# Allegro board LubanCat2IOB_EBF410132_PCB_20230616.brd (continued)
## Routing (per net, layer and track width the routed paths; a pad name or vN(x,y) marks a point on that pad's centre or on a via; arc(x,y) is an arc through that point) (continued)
HDMI_TX_HPD_PORT: length 8.2
  TOP w0.156: R172.2 53.41,76.45 54.55,76.45 R176.1 D15.2 56.16,80.11 J21.19
HDMI_TX_HPDIN: length 32.5
  TOP w0.156: v1(52.72,69.72) 52.72,75.24 51.85,76.11 R172.1 ; J3.34 v1(40.28,57.94)
  BOTTOM w0.156: v1(52.72,69.72) 52.72,68.69 52.41,68.37 50.14,68.37 49.71,67.94 49.71,60.56 49.29,60.14 40.6,60.14 40.28,59.83 v1(40.28,57.94)
HDMI_TXCLKN_PORT: length 68.3
  TOP w0.124: J21.12 56.61,85.53 59.32,85.53 60.19,84.67 60.19,80.48 58.78,79.07 58.78,77.99 58.69,77.9 U31.5 U31.6 58.69,76.17 58.78,76.08 58.78,70.07 v1(58.48,69.77) ; v1(44.78,57) 44.28,57.5 J3.50
  ART04 w0.113: v1(44.78,57) 45.09,57.31 46.91,57.31 47.35,57.74 47.35,59.14 47.03,59.46 45.15,59.46 45.02,59.59 45.02,59.78 45.15,59.91 47.03,59.91 47.35,60.23 47.35,65.25 47.59,65.49 47.9,65.49 48.04,65.36 48.04,63.84 48.38,63.5 48.82,63.5 49.12,63.79 49.12,65.36 49.25,65.49 49.44,65.49 49.57,65.36 49.57,63.84 49.91,63.5 50.36,63.5 50.65,63.79 50.65,65.36 50.79,65.49 50.97,65.49 51.1,65.36 51.1,63.84 51.45,63.5 51.89,63.5 52.19,63.79 52.19,65.36 52.32,65.49 52.51,65.49 52.64,65.36 52.64,63.84 52.98,63.5 53.42,63.5 53.72,63.79 53.72,65.36 53.85,65.49 55.12,65.49 55.64,66.01 55.64,70.44 55.82,70.62 58.59,70.62 58.78,70.43 58.78,70.08 v1(58.48,69.77)
HDMI_TXCLKP_PORT: length 69.3
  TOP w0.124: v1(59.4,69.77) 59.33,69.77 59.1,70 59.1,70.32 arc(59.14,70.42) 59.24,70.46 arc(59.34,70.5) 59.39,70.6 59.39,70.82 arc(59.34,70.92) 59.24,70.96 arc(59.14,71) 59.1,71.1 59.1,71.31 arc(59.14,71.41) 59.24,71.45 arc(59.34,71.49) 59.39,71.59 59.39,71.81 arc(59.34,71.91) 59.24,71.95 arc(59.14,71.99) 59.1,72.09 59.1,72.3 arc(59.14,72.4) 59.24,72.45 arc(59.34,72.49) 59.39,72.59 59.39,72.8 arc(59.34,72.9) 59.24,72.94 arc(59.14,72.98) 59.1,73.08 59.1,76.08 59.19,76.17 U31.7 U31.4 59.19,77.9 59.1,77.99 59.1,78.93 60.51,80.34 60.51,84.8 59.46,85.86 56.61,85.86 J21.10 ; v1(44.78,57.93) 44.78,57.94 J3.52
  ART04 w0.113: v1(59.4,69.77) 59.1,70.08 59.1,70.57 58.72,70.94 55.69,70.94 55.32,70.57 55.32,66.14 54.99,65.81 53.72,65.81 53.41,65.49 53.41,63.92 53.29,63.81 53.11,63.81 52.96,63.97 52.96,65.49 52.64,65.81 52.19,65.81 51.87,65.49 51.87,63.92 51.76,63.81 51.58,63.81 51.42,63.97 51.42,65.49 51.1,65.81 50.66,65.81 50.34,65.49 50.34,63.92 50.23,63.81 50.04,63.81 49.89,63.97 49.89,65.49 49.57,65.81 49.12,65.81 48.8,65.49 48.8,63.92 48.69,63.81 48.51,63.81 48.35,63.97 48.35,65.49 48.04,65.81 47.46,65.81 47.03,65.38 47.03,60.36 46.9,60.23 45.02,60.23 44.7,59.91 44.7,59.46 45.02,59.14 46.9,59.14 47.03,59.01 47.03,57.87 46.78,57.63 45.09,57.63 v1(44.78,57.93)
HDMI_TXDDC_SCL_PORT: length 11
  BOTTOM w0.156: Q6.3 55.02,74.6 R179.2 54.31,75.31 D17.2 54.81,76.68 54.81,78.99 54.28,79.52 54.28,83.03 54.63,83.38 J21.15
HDMI_TXDDC_SDA_PORT: length 11.6
  BOTTOM w0.156: Q8.3 58.32,74.6 R182.2 59.03,75.31 D16.2 59.03,76.17 59.03,81 58.63,81.4 57.34,81.4 57.1,81.63 57.1,82.52 56.82,82.8 J21.16
HDMITX_CEC_M0: length 32
  TOP w0.156: v1(40.28,56.94) 39.78,57.44 J3.32
  BOTTOM w0.156: v1(40.28,56.94) 40.84,57.5 40.84,59.32 41.16,59.64 49.88,59.64 50.19,59.95 50.19,67.46 50.62,67.89 53.24,67.89 53.59,68.25 53.59,69.89 53.28,70.2 51.49,70.2 R180.2 50.51,71.19 Q7.2
HDMITX_SCL: length 32.1
  TOP w0.156: J3.30 v1(39.28,57.94)
  BOTTOM w0.156: Q6.2 54.06,71.19 R178.2 54.52,68.25 53.72,67.46 51.31,67.46 50.72,66.87 50.72,59.48 50.41,59.17 41.69,59.17 41.38,58.85 41.38,56.67 41.06,56.36 40.08,56.36 39.77,56.67 39.77,57.45 v1(39.28,57.94)
HDMITX_SDA: length 36
  TOP w0.156: v1(39.28,56.94) 38.78,57.44 J3.28
  BOTTOM w0.156: Q8.2 57.37,71.19 R181.2 57.76,70.74 57.22,70.2 55.55,70.2 55.09,69.74 55.09,68.09 54.05,67.05 51.77,67.05 51.28,66.57 51.28,59.06 50.97,58.75 42.25,58.75 41.94,58.43 41.94,56.32 41.57,55.95 39.61,55.95 39.29,56.27 39.29,56.93 v1(39.28,56.94)
HP_DET: length 120.4
  TOP w0.156: J1.35 v1(40.78,23.89)
  ART03 w0.142: v1(40.78,23.89) 42.8,25.91 42.8,33.82 34.65,41.98 14.38,41.98 14.1,42.26 14.1,47.39 13.23,48.26 13.23,72.51 14.15,73.43 21.13,73.43 22.17,74.47 29.36,74.47 31.6,76.7 31.6,87.15 v1(32.11,87.66)
  BOTTOM w0.156: R211.1 40.39,92.34 C213.1 39.55,91.5 39.55,87.37 39.22,87.04 33.45,87.04 32.83,87.66 v1(32.11,87.66)
HP_SNS: length 130.1
  TOP w0.203: J1.36 v1(40.78,27.89)
  TOP w0.508: R216.1 R212.1 49.44,96.8 J27.5 43.78,96.78 J25.5
  ART03 w0.254: J25.5 34.71,96.78 33.27,95.35 31.17,95.35 30.53,94.71 30.53,88.36 30,87.83 26.9,87.83 26.19,87.12 22.63,87.12 22.07,86.56 22.07,76.3 20.4,74.62 13.64,74.62 11.94,72.92 11.94,47.65 12.75,46.83 12.75,40.92 13.28,40.38 34.59,40.38 41.35,33.63 41.35,30.32 40.18,29.16 40.18,28.47 40.76,27.89 v1(40.78,27.89)
HPL_OUT: length 91.6
  TOP w0.156: v1(40.78,30.89) 40.28,30.39 J1.34
  TOP w0.254: C214.1 21.49,81.5 21.84,81.15 21.84,76.63 21.59,76.37 v1(21.16,76.37)
  ART03 w0.254: v1(40.78,30.89) 40.78,33.41 34.32,39.87 12.8,39.87 12.24,40.43 12.24,46.63 11.42,47.45 11.42,73.14 13.36,75.08 19.86,75.08 v1(21.16,76.37)
HPR_OUT: length 92.5
  TOP w0.156: v1(40.78,28.89) 41.28,28.39 J1.38
  TOP w0.254: v1(22.99,76.37) 22.5,76.37 22.25,76.63 22.25,81.25 22.5,81.5 C215.1
  ART03 w0.254: v1(40.78,28.89) 41.86,29.97 41.86,33.88 34.8,40.94 13.75,40.94 13.28,41.4 13.28,47.14 12.42,48 12.42,72.79 13.79,74.16 20.78,74.16 v1(22.99,76.37)
HUB_3V3: length 23.3
  TOP w0.305: 102.79,97.02 103.61,97.84 v1(105.74,97.84) 110.04,97.84 v1(110.1,97.9) 115.4,97.9 v1(115.87,98.37) ; 102.79,97.02 v1(102.23,97.58) ; 102.79,97.02 102.79,96.08 v1(102.23,95.52)
  BOTTOM w0.305: R168.2 v1(110.1,97.9) ; R165.2 v1(102.23,97.58) ; v1(105.74,97.84) 106.09,98.18 C156.1 C157.1 106.95,98.44 U28.20 ; v1(115.87,98.37) 115.69,98.56 R169.1 ; R166.2 v1(102.23,95.52) R164.2
I2C0_SCL: length 117.9
  TOP w0.156: v1(54.78,23.89) 55.27,24.38 57.48,24.38 57.78,24.08 J2.3
  ART03 w0.142: v1(54.78,23.89) 54.78,23.06 54.12,22.39 39.59,22.39 39.31,22.67 39.31,24.71 37.76,26.26 37.76,34.76 33.82,38.69 9.94,38.69 9.65,38.98 9.65,73 9.04,73.61 9.04,74.82 8.46,75.41 8.46,83.33 8.79,83.66 14.53,83.66 v1(15.37,84.5)
  BOTTOM w0.156: U17.6 v1(15.37,84.5)
I2C0_SDA: length 121.7
  TOP w0.156: J2.5 58.28,24.21 57.78,24.71 54.96,24.71 v1(54.78,24.89)
  ART03 w0.142: v1(54.78,24.89) 55.3,24.38 55.3,22.93 54.31,21.94 38.59,21.94 38.31,22.23 38.31,24.35 36.93,25.73 36.93,34.39 33.83,37.49 8.96,37.49 8.67,37.77 8.67,73.19 8.08,73.78 8.08,83.94 8.51,84.37 13.97,84.37 v1(14.1,84.5)
  BOTTOM w0.156: U17.5 v1(14.1,84.5)
I2C1_SCL: length 180.7
  TOP w0.156: R35.2 58.78,20.09 J2.7 58.78,24.4 58.13,25.05 55.52,25.05 55.22,25.35 55.22,27.25 54.99,27.48 54.04,27.48 v1(54,27.51) ; 156.31,67.91 156.31,53.3 155.5,52.48 v1(154.54,52.48) 154.05,51.99 154.05,49.35 156.34,47.06 156.34,36.57 155.78,36.01 146.94,36.01 v1(146.71,36.24) ; J23.9 155.8,68.43
  TOP w0.173: 155.8,68.43 156.31,67.91
  ART03 w0.142: v1(146.71,36.24) 146.2,36.75 142.43,36.75 142.19,36.51 142.19,35.63 141.86,35.3 133.93,35.3 132.92,34.29 132.92,27.99 132.64,27.71 121.89,27.71 120.55,26.36 108.1,26.36 106.58,27.89 95.33,27.89 95.05,27.6 95.05,21.76 94.63,21.35 79.36,21.35 79.07,21.64 79.07,25.07 78.64,25.5 68.4,25.5 67.21,26.69 62.57,26.69 62.28,26.98 62.28,29.08 62,29.37 54.29,29.37 54,29.08 v1(54,27.51)
  BOTTOM w0.156: J22.6 153.24,53.78 v1(154.54,52.48)
I2C1_SDA: length 169.1
  TOP w0.156: v1(59.78,24.89) 59.28,24.39 J2.9 59.28,20.08 R33.2 ; 156.64,52.13 156,51.48 v1(154.54,51.48) 154.54,49.55 156.68,47.42 156.68,36.12 156.14,35.58 146.37,35.58 v1(145.71,36.24) ; J23.10 156,68.93
  TOP w0.173: 156.64,52.13 156.64,68.29 156,68.93
  ART03 w0.142: v1(145.71,36.24) 145.71,35.25 145.43,34.97 134.13,34.97 133.3,34.13 133.3,30.3 133.91,29.69 133.91,21.59 133.43,21.1 126.57,21.1 125.93,21.74 123.93,21.74 123.29,21.1 103.66,21.1 102.64,20.09 97.38,20.09 96.44,21.03 78.99,21.03 78.71,21.31 78.71,24.03 78.37,24.38 67.57,24.38 67.28,24.67 67.28,26.08 67,26.36 60.6,26.36 59.78,25.54 v1(59.78,24.89)
  BOTTOM w0.156: v1(154.54,51.48) 154.03,52 154.03,52.37 153.12,53.28 J22.5
I2C5_SCL_M0: length 220
  TOP w0.156: v1(64.26,60.92) 63.28,61.9 J4.25 63.28,65.97 62.79,66.47 61.02,66.47 R147.2 ; J26.9 152.74,45.69 v1(152.85,45.59) ; v1(79.78,27.89) 80.49,28.6 91.82,28.6 93.75,26.67 93.75,18.27 94.06,17.95 106.64,17.95 106.95,17.64 J28.4
  ART03 w0.142: v1(152.85,45.59) 153.39,45.05 153.39,32.08 151.46,30.15 151.46,16.89 152.3,16.05 152.3,14.09 151.87,13.66 147.35,13.66 146.35,14.65 140.28,14.65 139.06,13.43 108.13,13.43 J28.4
  BOTTOM w0.156: v1(152.85,45.59) 152.97,45.59 154.1,45.59 154.41,45.89 154.41,47.64 154.72,47.95 156.24,47.95 156.67,48.38 ; v1(64.26,60.92) 62.8,60.92 60.91,59.03 60.91,50.62 61.62,49.91 71.98,49.91 72.29,49.6 72.29,26.65 72.6,26.34 78.1,26.34 78.3,26.53 78.3,27.11 78.56,27.38 79.27,27.38 v1(79.78,27.89) ; J24.6 155.12,71.98 156.67,70.43
  BOTTOM w0.173: 156.67,70.43 156.67,48.38
I2C5_SDA_M0: length 220.6
  TOP w0.156: v1(78.78,26.89) 79.63,26.89 80.87,28.14 91.77,28.14 93.4,26.51 93.4,17.78 93.71,17.47 104.64,17.47 104.95,17.16 J28.5 ; J26.10 153.82,46.19 v1(153.85,46.22) ; v1(64.26,61.87) 63.98,61.87 63.78,62.07 J4.27 63.78,66.08 63.09,66.78 61.78,66.78 R146.2
  ART03 w0.142: v1(153.85,46.22) 154.15,45.91 154.15,31.9 152.07,29.82 152.07,17.24 152.91,16.4 152.91,13.92 152.1,13.1 146.89,13.1 145.92,14.07 140.64,14.07 139.45,12.87 117.26,12.87 116.78,12.4 107.17,12.4 J28.5
  BOTTOM w0.156: v1(78.78,26.89) 78.78,26.18 78.44,25.83 72.22,25.83 71.91,26.14 71.91,49.07 71.45,49.53 61.34,49.53 60.55,50.31 60.55,59.28 62.63,61.36 63.75,61.36 v1(64.26,61.87) ; v1(153.85,46.22) 153.85,48.02 154.16,48.33 155.97,48.33 156.29,48.65 156.29,70.28 155.08,71.48 J24.5
LCD0_BL_PWM: length 164.8
  TOP w0.156: v1(156.17,85.43) 156.69,84.92 156.69,73.8 156.69,73.79 156.69,70.33 156.29,69.92 154.66,69.92 154.16,70.43 J23.13 ; J3.9 34.28,65.44 v1(33.78,65.94)
  ART03 w0.142: v1(156.17,85.43) 153.68,85.43 153.39,85.72 153.39,87.35 152.96,87.78 138.81,87.78 132.62,81.59 119.89,81.59 119.2,80.9 98.12,80.9 97.38,80.16 96.37,80.16 96.09,80.44 87.5,80.44 86.23,79.17 77.14,79.17 75.79,80.51 67.18,80.51 66.04,79.37 61.26,79.37 60.99,79.09 60.99,77.42 60.48,76.91 35.29,76.91 34.21,75.84 34.21,70.2 33.78,69.77 v1(33.78,65.94)
LCD0_PWR_EN: length 164.4
  TOP w0.156: R195.1 140.6,61.5 v1(140.84,61.74) ; J4.65 v1(73.28,64.94)
  ART03 w0.142: v1(73.28,64.94) 73.28,64.16 73.57,63.88 75.98,63.88 76.26,63.59 76.26,58.86 77.42,57.7 86.91,57.7 87.2,57.99 87.2,60.95 87.48,61.23 95.61,61.23 v1(96.09,60.75) ; v1(146.71,38.24) 146.22,38.73 141.38,38.73 141.2,38.55 141.2,36.27 140.94,36.01 133.53,36.01 131.88,34.36 131.88,30.17 130.38,28.67 94.98,28.67 v1(94.8,28.85)
  BOTTOM w0.156: v1(146.71,38.24) 150.59,38.24 150.9,38.55 150.9,47.97 150.59,48.28 141.6,48.28 141.12,48.76 141.12,61.46 v1(140.84,61.74) ; v1(96.09,60.75) 95.61,60.27 95.61,29.65 v1(94.8,28.85)
LCD1_BL_PWM: length 145.2
  TOP w0.156: J3.11 34.78,62.13 34.63,61.97 31.88,61.97 31.5,61.59 31.5,58.16 32.28,57.37 32.28,49.66 32.6,49.35 96.16,49.35 98.55,51.74 108.04,51.74 108.36,51.42 108.36,46.67 108.67,46.36 v1(121.42,46.36) ; J26.13 v1(149.43,47.69)
  BOTTOM w0.156: v1(121.42,46.36) 122.5,45.28 138.35,45.28 138.79,45.72 138.79,47.67 139.06,47.95 149.17,47.95 v1(149.43,47.69)
LCD1_PWR_EN: length 98.1
  TOP w0.156: v1(92.09,59.75) 91.49,59.16 91.49,57.37 91.9,56.97 94.34,56.97 95.43,58.06 111.84,58.06 112.15,57.75 112.15,50.98 112.46,50.67 123.56,50.67 123.93,50.3 123.93,43.82 124.24,43.51 137.41,43.51 137.72,43.19 137.72,39.35 138.03,39.04 R200.2 ; J4.67 v1(73.78,61.94)
  ART03 w0.142: v1(73.78,61.94) 73.78,56.85 74.07,56.56 88.18,56.56 88.47,56.85 88.47,59.48 88.75,59.76 92.08,59.76 v1(92.09,59.75)
LED_USR: length 128
  TOP w0.156: J4.4 57.78,54.79 58.1,54.48 93.52,54.48 96.34,57.3 107.82,57.3 v1(108.31,56.8) ; LED2.2 v1(139.07,98.39)
  BOTTOM w0.156: v1(108.31,56.8) 108.31,64.02 108.63,64.33 116.81,64.33 117.3,64.82 117.3,69.44 118.06,70.2 121.78,70.2 122.1,70.51 122.1,77.18 122.41,77.49 134.69,77.49 135,77.8 135,93.78 135.31,94.09 138.7,94.09 139.06,94.46 139.06,98.38 v1(139.07,98.39)
M2PCIE_3V3: length 47.2
  TOP w0.305: J17.16 140.4,83.64 v1(140.65,83.4) 140.9,83.65 J17.18 ; v1(139.45,80.44) 138.65,80.44 138.44,80.22 R86.1 R85.1 ; C69.2 R73.2 v1(135.2,57.59) ; J17.14 139.9,83.65 v1(139.65,83.4) 139.4,83.64 J17.12 ; J17.2 136.9,83.64 v1(137.15,83.4) 137.4,83.65 J17.4 ; v1(139.95,71.72) 139.96,71.73 R83.1 ; U21.1 v1(142.49,79.17)
  ART04 w0.305: v1(135.2,57.59) 136.46,57.59 137.11,58.24 137.11,68.25 137.08,68.27
  BOTTOM w0.305: v1(139.94,87.15) 140.18,86.91 R81.2 ; C116.1 C115.1 ; v1(138.75,69.69) 138.76,69.69
  BOTTOM w0.381: C130.1 C131.1 C129.1 ; v1(152.15,85.79) 152.15,84.76 151.66,84.27 148.06,84.27 147.46,83.67 C136.1 R145.2 142.88,78.79 v1(142.49,79.17)
  BOTTOM w0.508: v1(139.95,71.72) 140,71.67 R84.1
  vias: v1(136.75,69.69) v1(137.75,69.69) v1(138.75,68.69) v1(152.15,86.79) v1(154.18,87.15) v1(154.18,86.15)
M2PCIE_PWR_EN: length 191.7
  TOP w0.156: J1.41 42.28,21.16 44.34,19.1 44.34,10.55 v1(44.05,10.26)
  ART03 w0.142: v1(128.18,10.5) 92.75,10.5 90.3,8.05 82.6,8.05 81,9.65 44.66,9.65 v1(44.05,10.26)
  BOTTOM w0.156: v1(128.18,10.5) 128.18,13.5 128.49,13.81 147.74,13.81 148.06,14.13 148.06,23.01 148.51,23.47 151.25,23.47 151.59,23.8 151.59,49.39 151.25,49.73 145.08,49.73 144.78,50.03 144.78,57.85 144.56,58.06 142.57,58.06 142.27,58.37 142.27,63.97 141.93,64.31 137.13,64.31 136.79,63.97 R76.2
MDIN0_PHY0: length 6.5
  TOP w0.124: U18.2 72.29,79.64 72.33,79.68 72.33,80.02 73.84,81.53 73.84,82.75 73.38,83.21 72.95,83.21 72.82,83.08 72.82,82.23 J11.3
MDIN0_PHY1: length 6.2
  TOP w0.124: J18.3 91.11,82.22 91.11,83.08 91.23,83.21 91.69,83.21 92.15,82.75 92.15,80.73 91.5,80.08 91.5,79.68 91.47,79.64 U19.2
MDIN1_PHY0: length 13.2
  TOP w0.124: J11.7 67.76,85.49 68.12,85.85 69.88,85.85 70.16,85.57 70.16,84.06 71.43,82.79 71.43,81.13 71.13,80.83 71.13,79.68 71.09,79.64 U18.5
MDIN1_PHY1: length 13.2
  TOP w0.124: U19.5 90.27,79.64 90.3,79.68 90.3,80.71 89.67,81.35 89.67,82.7 88.34,84.02 88.34,85.64 88.22,85.76 86.3,85.76 86.02,85.49 J18.7
MDIN2_PHY0: length 6.4
  TOP w0.124: J11.6 68.96,84.68 68.96,81.62 70.33,80.26 70.33,79.68 70.29,79.64 U18.7
MDIN2_PHY1: length 7.4
  TOP w0.124: U19.7 89.47,79.64 89.5,79.68 89.5,80.37 89.13,80.75 88.01,80.75 87.2,81.56 87.2,84.65 J18.6
MDIN3_PHY0: length 8.4
  TOP w0.124: U18.10 69.09,79.64 69.13,79.68 69.13,79.83 68.88,80.08 66.75,80.08 66.24,80.59 66.24,82.77 65.81,83.21 65.35,83.21 65.22,83.08 J11.9
MDIN3_PHY1: length 9.2
  TOP w0.124: J18.9 83.48,83.08 83.61,83.21 84.07,83.21 84.51,82.77 84.51,80.66 85.26,79.9 88.16,79.9 88.28,79.78 88.28,79.66 88.27,79.64 U19.10
MDIP0_PHY0: length 6.4
  TOP w0.124: U18.1 72.69,79.64 72.66,79.68 72.66,79.88 74.17,81.4 74.17,84.7 J11.2
MDIP0_PHY1: length 6.1
  TOP w0.124: U19.1 91.87,79.64 91.83,79.68 91.83,79.94 92.48,80.59 92.48,84.64 J18.2
MDIP1_PHY0: length 13.1
  TOP w0.124: U18.4 71.49,79.64 71.45,79.68 71.45,80.7 71.75,81 71.75,82.93 70.48,84.2 70.48,86.25 70.71,86.48 72.52,86.48 72.85,86.15 72.85,84.98 72.61,84.75 J11.4
MDIP1_PHY1: length 13.1
  TOP w0.124: J18.4 90.94,84.75 91.06,84.87 91.06,86.18 90.86,86.38 88.87,86.38 88.67,86.18 88.67,84.15 89.99,82.83 89.99,81.48 90.63,80.85 90.63,79.68 90.67,79.64 U19.4
MDIP2_PHY0: length 6.5
  TOP w0.124: J11.5 70.31,82.21 70.31,83.08 70.18,83.21 69.72,83.21 69.29,82.77 69.29,81.76 70.66,80.4 70.66,79.68 70.69,79.64 U18.6
MDIP2_PHY1: length 7.5
  TOP w0.124: U19.6 89.87,79.64 89.83,79.68 89.83,80.5 89.26,81.07 88.14,81.07 87.53,81.69 87.53,82.82 87.88,83.18 88.45,83.18 88.57,83.06 88.57,82.22 J18.5
MDIP3_PHY0: length 8.2
  TOP w0.124: J11.8 66.57,84.67 66.57,80.73 66.89,80.41 69.01,80.41 69.45,79.97 69.45,79.68 69.49,79.64 U18.9
MDIP3_PHY1: length 9.1
  TOP w0.124: U19.9 88.67,79.64 88.61,79.7 88.61,79.91 88.29,80.23 85.4,80.23 84.83,80.8 84.83,84.67 J18.8
MIC1_INN: length 87.2
  TOP w0.203: J1.30 39.28,27.59 39.23,27.65 39.23,46.09 38.3,47.01 31.59,47.01 31.09,47.51 31.09,54.61 v1(31.41,54.94) ; J27.4 43.9,90.6 J27.3 45.8,84.02 45.31,83.54 44.35,83.54 44.17,83.36 44.17,82.36 D30.1 44.02,81.61 44.02,79.43 J30.1
  BOTTOM w0.203: J30.1 44.84,78.6 44.07,77.83 44.07,75.69 C217.2 ; C217.2 44.02,74.47 44.02,74.11 43.59,73.69 37.98,73.69 37.41,73.12 37.41,64.41 36.68,63.67 33.73,63.67 33.33,63.27 33.33,59 31.11,56.79 31.11,55.24 v1(31.41,54.94) ; C217.2 R215.1
MIC1_INP: length 94.5
  TOP w0.203: v1(30.48,54.94) 30.73,54.69 30.73,47.37 31.45,46.66 38.1,46.66 38.87,45.89 38.87,27.61 38.78,27.53 J1.28 ; J27.2 42.31,94.3 41.55,93.54 41.55,85.31 41.87,85 J27.1 43.8,82.63 D29.1 43.66,81.64 43.66,79.41 J30.2
  BOTTOM w0.203: C217.1 43.65,74.5 43.65,74.27 43.43,74.04 37.83,74.04 37.75,73.96 37.72,73.96 37.06,73.3 37.06,73.27 37.06,64.61 36.5,64.05 33.58,64.05 32.97,63.45 32.97,59.15 30.76,56.93 30.76,55.21 v1(30.48,54.94) ; C217.1 43.69,75.74 43.69,77.77 42.86,78.6 J30.2 ; C217.1 R214.2
MINIPCIE_3V3: length 25.1
  TOP w0.508: v1(115.49,70.61) 116.3,69.8 J35.24 ; v1(128.36,70.54) 128.3,70.48 J35.2 ; J35.39 v1(110.3,75.31) ; J35.52 v1(105.1,66.85) ; J35.41 v1(109.5,75.31)
  ART04 w0.305: v1(123.3,61.68) 123.49,61.49 130.43,61.49
  BOTTOM w0.305: C55.1 105.16,66.78 v1(105.1,66.85) ; R14.1 C32.1 123.93,58.09 123.57,58.44 123.57,61.41 v1(123.3,61.68) ; C57.1 128.46,70.53 128.45,70.54 v1(128.36,70.54) R22.1
  BOTTOM w0.381: C56.1 115.47,70.63 v1(115.49,70.61)
  vias: v1(132.26,63.37) v1(132.26,62.37) v1(132.26,61.37) v1(133.26,61.37)
MINIPCIE_NWDISABLE: length 61.4
  TOP w0.156: v1(94.09,60.75) 94.57,60.27 97.63,60.27 97.94,60.58 97.94,62.52 98.26,62.84 117.58,62.84 117.98,63.24 R62.2 ; J4.61 v1(72.28,64.94)
  ART03 w0.142: v1(72.28,64.94) 72.28,63.63 72.67,63.24 75.02,63.24 75.31,62.96 75.31,57.61 75.59,57.32 87.29,57.32 87.58,57.61 87.58,60.47 87.86,60.75 v1(94.09,60.75)
MINIPCIE_PWR_EN: length 66.5
  TOP w0.156: v1(123.3,62.68) 123.1,62.48 98.76,62.48 98.45,62.17 98.45,60.07 98.14,59.75 v1(95.09,59.75) ; J4.63 v1(72.78,61.94)
  ART03 w0.142: v1(72.78,61.94) 73.26,61.46 73.26,56.47 73.55,56.18 88.64,56.18 88.93,56.47 88.93,58.92 89.21,59.2 94.54,59.2 v1(95.09,59.75)
  BOTTOM w0.156: v1(123.3,62.68) 123.3,62.68 124.46,62.68 124.72,62.42 R16.1
MIPI_CSI_RX_CLK0N: length 178.5
  TOP w0.124: v1(54.36,57.88) 54.06,57.58 51.44,57.58 51.2,57.82 51.2,58.16 51.28,58.25 J3.78
  ART03 w0.113: v1(155.52,55.74) 155.24,55.46 152.22,55.46 151.87,55.1 151.87,51.81 151.69,51.63 151.45,51.63 151.32,51.77 151.32,52.82 151,53.13 150.55,53.13 150.23,52.82 150.23,51.77 150.1,51.63 149.91,51.63 149.78,51.77 149.78,52.82 149.47,53.13 149.02,53.13 148.7,52.82 148.7,51.77 148.57,51.63 148.38,51.63 148.25,51.77 148.25,52.82 147.93,53.13 147.48,53.13 147.17,52.82 147.17,51.77 147.03,51.63 145.49,51.63 arc(145.4,51.67) 145.36,51.76 arc(145.33,51.85) 145.24,51.89 145.04,51.89 arc(144.95,51.85) 144.91,51.76 arc(144.87,51.67) 144.78,51.63 144.59,51.63 arc(144.5,51.67) 144.46,51.76 arc(144.42,51.85) 144.33,51.89 144.14,51.89 arc(144.05,51.85) 144.01,51.76 arc(143.97,51.67) 143.88,51.63 143.68,51.63 arc(143.6,51.67) 143.56,51.76 arc(143.52,51.85) 143.43,51.89 143.23,51.89 arc(143.14,51.85) 143.11,51.76 arc(143.07,51.67) 142.98,51.63 133.11,51.63 132.7,51.23 132.7,44.71 132.38,44.4 122.16,44.4 121.71,43.94 121.71,39.57 121.44,39.31 86.98,39.31 86.47,39.82 42.57,39.82 42.21,40.17 41.07,40.17 v1(40.77,40.47)
  BOTTOM w0.124: J22.10 152.27,55.78 152.36,55.69 153.37,55.69 153.55,55.52 155.3,55.52 v1(155.52,55.74) ; v1(40.77,40.47) 41.06,40.18 42.09,40.18 42.21,40.3 42.21,42.93 42.67,43.38 50.06,43.38 50.32,43.64 50.32,57.2 50.69,57.58 54.06,57.58 v1(54.36,57.88)
MIPI_CSI_RX_CLK0P: length 178.2
  TOP w0.124: v1(54.36,56.95) 54.06,57.25 51.3,57.25 50.87,57.69 50.87,58.16 50.78,58.25 J3.76
  ART03 w0.113: v1(40.77,39.55) 41.07,39.85 42.08,39.85 42.44,39.5 86.34,39.5 86.85,38.99 121.57,38.99 121.84,39.26 122.02,39.44 122.02,43.81 122.29,44.08 132.52,44.08 133.02,44.58 133.02,51.1 133.24,51.32 147.16,51.32 147.48,51.64 147.48,52.68 147.61,52.82 147.8,52.82 147.93,52.68 147.93,51.64 148.25,51.32 148.7,51.32 149.02,51.64 149.02,52.68 149.15,52.82 149.33,52.82 149.47,52.68 149.47,51.64 149.78,51.32 150.23,51.32 150.55,51.64 150.55,52.68 150.68,52.82 150.87,52.82 151,52.68 151,51.64 151.32,51.32 151.82,51.32 152.18,51.68 152.18,54.97 152.35,55.14 155.24,55.14 v1(155.52,54.85)
  BOTTOM w0.124: v1(54.36,56.95) 54.06,57.25 50.83,57.25 50.64,57.07 50.64,43.5 50.19,43.05 42.8,43.05 42.54,42.79 42.54,40.16 42.23,39.85 41.06,39.85 v1(40.77,39.55) ; v1(155.52,54.85) 155.18,55.19 153.41,55.19 153.24,55.37 152.36,55.37 152.27,55.28 J22.9
MIPI_CSI_RX_CLK1N: length 170.3
  TOP w0.124: v1(53.12,60.75) 53.42,61.05 53.42,65.46 53.29,65.58 51.33,65.58 51.2,65.44 51.2,64.72 51.28,64.63 J3.77
  ART03 w0.113: v1(144.63,74.41) 144.34,74.13 143.41,74.13 143.05,73.77 143.05,73.04 142.87,72.85 142.56,72.85 142.42,72.99 142.42,73.82 142.11,74.14 141.66,74.14 141.34,73.82 141.34,72.99 141.21,72.85 138.5,72.85 138.36,72.99 138.36,73.87 138.05,74.19 137.6,74.19 137.28,73.87 137.28,72.2 137.15,72.07 136.74,72.07 136.58,72.23 136.58,73.75 136.22,74.1 131.29,74.1 130.85,73.66 130.85,68.88 130.74,68.77 130.18,68.77 130.05,68.9 130.05,69.55 129.73,69.87 129.28,69.87 128.97,69.55 128.97,68.9 128.83,68.77 128.52,68.77 128.39,68.9 128.39,69.48 128.07,69.8 127.62,69.8 127.3,69.48 127.3,68.9 127.17,68.77 126.98,68.77 126.85,68.9 126.85,69.48 126.53,69.8 126.09,69.8 125.77,69.48 125.77,68.9 125.64,68.77 125.45,68.77 125.32,68.9 125.32,69.48 125,69.8 124.55,69.8 124.23,69.48 124.23,68.9 124.1,68.77 123.92,68.77 123.78,68.9 123.78,69.48 123.47,69.8 123.02,69.8 122.7,69.48 122.7,68.9 122.57,68.77 122.38,68.77 122.25,68.9 122.25,69.48 121.93,69.8 121.48,69.8 121.17,69.48 121.17,68.9 121.03,68.77 120.85,68.77 120.72,68.9 120.72,69.48 120.4,69.8 119.95,69.8 119.63,69.48 119.63,68.9 119.5,68.77 119.31,68.77 119.18,68.9 119.18,69.48 118.86,69.8 118.42,69.8 118.1,69.48 118.1,68.9 117.97,68.77 113.2,68.77 112.9,68.47 112.9,62.3 112.13,61.53 99.88,61.53 99.42,61.07 99.42,54.77 98.95,54.31 95.8,54.31 95.5,54.01 95.5,49.93 95.17,49.6 55.5,49.6 55.36,49.74 55.36,50.27 55.49,50.4 56.35,50.4 56.67,50.72 56.67,51.16 56.35,51.48 55.49,51.48 55.36,51.61 55.36,51.8 55.49,51.93 56.35,51.93 56.67,52.25 56.67,52.7 56.35,53.02 55.49,53.02 55.36,53.15 55.36,53.34 55.49,53.47 56.35,53.47 56.67,53.78 56.67,58.79 arc(56.69,58.85) 56.76,58.88 arc(56.82,58.91) 56.85,58.97 56.85,59.24 arc(56.82,59.31) 56.76,59.33 arc(56.69,59.36) 56.67,59.42 56.67,59.69 arc(56.69,59.76) 56.76,59.78 arc(56.82,59.81) 56.85,59.87 56.85,60.14 arc(56.82,60.21) 56.76,60.23 arc(56.69,60.26) 56.67,60.32 56.67,60.6 arc(56.69,60.66) 56.76,60.68 arc(56.82,60.71) 56.85,60.77 56.85,61.05 arc(56.82,61.11) 56.76,61.14 arc(56.69,61.16) 56.67,61.22 56.67,61.46 56.33,61.81 53.79,61.81 53.42,61.43 53.42,61.05 v1(53.12,60.75)
  BOTTOM w0.124: J24.10 150.59,73.98 150.5,73.89 150.18,73.89 149.94,74.14 144.9,74.14 v1(144.63,74.41)
MIPI_CSI_RX_CLK1P: length 170.3
  TOP w0.124: v1(54.04,60.75) 53.74,61.05 53.74,65.59 53.43,65.91 51.2,65.91 50.87,65.58 50.87,64.72 50.78,64.63 J3.75
  ART03 w0.113: v1(144.63,73.52) 144.34,73.81 143.54,73.81 143.37,73.64 143.37,72.91 143,72.54 142.42,72.54 142.11,72.86 142.11,73.69 141.97,73.82 141.79,73.82 141.66,73.69 141.66,72.86 141.34,72.54 138.37,72.54 138.05,72.86 138.05,73.74 137.92,73.87 137.73,73.87 137.6,73.74 137.6,72.07 137.28,71.75 136.61,71.75 136.26,72.1 136.26,73.62 136.09,73.78 131.42,73.78 131.17,73.53 131.17,68.75 130.87,68.45 130.05,68.45 129.73,68.77 129.73,69.42 129.6,69.56 129.41,69.56 129.28,69.42 129.28,68.77 128.97,68.45 128.39,68.45 128.07,68.77 128.07,69.35 127.94,69.48 127.75,69.48 127.62,69.35 127.62,68.77 127.3,68.45 126.85,68.45 126.54,68.77 126.54,69.35 126.4,69.48 126.22,69.48 126.09,69.35 126.09,68.77 125.77,68.45 125.32,68.45 125,68.77 125,69.35 124.87,69.48 124.68,69.48 124.55,69.35 124.55,68.77 124.23,68.45 123.79,68.45 123.47,68.77 123.47,69.35 123.34,69.48 123.15,69.48 123.02,69.35 123.02,68.77 122.7,68.45 122.25,68.45 121.93,68.77 121.93,69.35 121.8,69.48 121.61,69.48 121.48,69.35 121.48,68.77 121.17,68.45 120.72,68.45 120.4,68.77 120.4,69.35 120.27,69.48 120.08,69.48 119.95,69.35 119.95,68.77 119.63,68.45 119.18,68.45 118.87,68.77 118.87,69.35 118.73,69.48 118.55,69.48 118.41,69.35 118.41,68.77 118.1,68.45 113.33,68.45 113.22,68.34 113.22,62.17 112.26,61.22 100.01,61.22 99.73,60.94 99.73,54.64 99.09,54 95.93,54 95.82,53.88 95.82,49.8 95.3,49.29 55.37,49.29 55.04,49.61 55.04,50.4 55.36,50.72 56.22,50.72 56.35,50.85 56.35,51.03 56.22,51.17 55.36,51.17 55.04,51.48 55.04,51.93 55.36,52.25 56.22,52.25 56.35,52.38 56.35,52.57 56.22,52.7 55.36,52.7 55.04,53.02 55.04,53.47 55.36,53.78 56.22,53.78 56.35,53.92 56.35,61.33 56.2,61.49 53.92,61.49 53.74,61.3 53.74,61.05 v1(54.04,60.75)
  BOTTOM w0.124: J24.9 150.59,73.48 150.5,73.57 150.04,73.57 149.8,73.81 144.92,73.81 v1(144.63,73.52)
MIPI_CSI_RX_D0N: length 178.1
  TOP w0.124: J3.70 49.28,58.25 49.2,58.16 49.2,56.38 v1(49.5,56.08)
  ART03 w0.113: v1(40.77,42.6) 41.07,42.3 42.17,42.3 43.35,41.12 87.8,41.12 88.32,40.6 120.18,40.6 120.45,40.86 120.45,45.17 120.84,45.56 124.37,45.56 124.58,45.77 124.58,53.96 125.2,54.58 148.85,54.58 arc(148.91,54.61) 148.94,54.67 arc(148.97,54.73) 149.03,54.76 149.3,54.76 arc(149.37,54.73) 149.39,54.67 arc(149.42,54.61) 149.48,54.58 149.75,54.58 arc(149.82,54.61) 149.84,54.67 arc(149.87,54.73) 149.93,54.76 150.2,54.76 arc(150.27,54.73) 150.29,54.67 arc(150.32,54.61) 150.38,54.58 150.62,54.58 150.81,54.77 150.81,56.39 151.2,56.78 154.18,56.78 v1(154.46,57.06)
  BOTTOM w0.124: v1(154.46,57.06) 154.09,56.69 152.36,56.69 152.27,56.78 J22.12 ; v1(49.5,56.08) 49.2,55.78 49.2,55.01 48.86,54.67 47.51,54.67 47.37,54.53 47.37,54.32 47.51,54.18 48.86,54.18 49.2,53.84 49.2,53.37 48.86,53.03 47.51,53.03 47.37,52.88 47.37,52.68 47.51,52.53 48.86,52.53 49.2,52.2 49.2,51.72 48.86,51.38 47.51,51.38 47.37,51.24 47.37,51.03 47.51,50.89 48.86,50.89 49.2,50.55 49.2,50.07 48.86,49.74 47.79,49.74 47.65,49.59 47.65,49.39 47.79,49.24 48.86,49.24 49.2,48.9 49.2,48.43 48.86,48.09 47.79,48.09 47.65,47.95 47.65,47.74 47.79,47.6 48.86,47.6 49.2,47.26 49.2,46.78 48.86,46.45 47.79,46.45 47.65,46.3 47.65,46.09 47.79,45.95 48.86,45.95 49.2,45.61 49.2,44.94 48.88,44.62 39.93,44.62 39.55,44.24 39.55,42.45 39.69,42.31 40.47,42.31 v1(40.77,42.6)
MIPI_CSI_RX_D0P: length 178.1
  TOP w0.124: J3.68 48.78,58.25 48.87,58.16 48.87,56.38 v1(48.57,56.08)
  ART03 w0.113: v1(154.46,56.17) 154.18,56.46 151.33,56.46 151.13,56.26 151.13,54.64 150.75,54.26 125.33,54.26 124.89,53.83 124.89,45.64 124.5,45.25 120.97,45.25 120.76,45.04 120.76,40.73 120.31,40.28 88.19,40.28 87.66,40.8 43.21,40.8 42.03,41.98 41.07,41.98 v1(40.77,41.69)
  BOTTOM w0.124: v1(40.77,41.69) 40.47,41.98 39.55,41.98 39.22,42.31 39.22,44.38 39.79,44.95 48.75,44.95 48.87,45.08 48.87,45.48 48.73,45.62 47.66,45.62 47.32,45.96 47.32,46.44 47.66,46.77 48.73,46.77 48.87,46.92 48.87,47.12 48.73,47.27 47.66,47.27 47.32,47.61 47.32,48.08 47.66,48.42 48.73,48.42 48.87,48.56 48.87,48.77 48.73,48.91 47.66,48.91 47.32,49.25 47.32,49.73 47.66,50.06 48.73,50.06 48.87,50.21 48.87,50.41 48.73,50.56 47.38,50.56 47.04,50.9 47.04,51.37 47.38,51.71 48.73,51.71 48.87,51.86 48.87,52.06 48.73,52.21 47.38,52.21 47.04,52.54 47.04,53.02 47.38,53.36 48.73,53.36 48.87,53.5 48.87,53.71 48.73,53.85 47.38,53.85 47.04,54.19 47.04,54.67 47.38,55 48.73,55 48.87,55.15 48.87,55.78 v1(48.57,56.08) ; J22.11 152.27,56.28 152.36,56.37 154.27,56.37 v1(154.46,56.17)
MIPI_CSI_RX_D1N: length 178.2
  TOP w0.124: J3.74 50.28,58.25 50.2,58.16 50.2,57.3 51.34,56.16 52.46,56.16 v1(52.76,56.46)
  ART03 w0.113: v1(154.54,54.37) 154.26,54.08 153.72,54.08 153.33,53.7 153.33,50.35 153.14,50.16 152.8,50.16 arc(152.72,50.19) 152.68,50.28 arc(152.65,50.36) 152.57,50.39 152.35,50.39 arc(152.26,50.36) 152.23,50.28 arc(152.2,50.19) 152.12,50.16 151.89,50.16 arc(151.81,50.19) 151.78,50.28 arc(151.75,50.36) 151.67,50.39 151.44,50.39 arc(151.36,50.36) 151.33,50.28 arc(151.3,50.19) 151.21,50.16 150.97,50.16 arc(150.89,50.19) 150.86,50.28 arc(150.83,50.36) 150.75,50.39 150.52,50.39 arc(150.44,50.36) 150.41,50.28 arc(150.38,50.19) 150.29,50.16 135.19,50.16 134.81,49.78 134.81,43.5 134.52,43.2 123.78,43.2 123.36,42.77 123.36,38.42 123.12,38.18 85.79,38.18 85.46,38.51 42.74,38.51 42.35,38.12 41.09,38.12 v1(40.79,38.42)
  BOTTOM w0.124: J22.8 152.27,54.78 152.36,54.69 153.46,54.69 154.05,54.1 154.27,54.1 v1(154.54,54.37) ; v1(52.76,56.46) 52.46,56.16 51.71,56.16 51.36,55.81 51.36,42.4 51.18,42.21 48.87,42.21 48.53,41.87 48.53,40.42 48.39,40.28 48.18,40.28 48.04,40.42 48.04,41.87 47.7,42.21 47.22,42.21 46.89,41.87 46.89,40.42 46.74,40.28 46.54,40.28 46.39,40.42 46.39,41.87 46.05,42.21 45.58,42.21 45.24,41.87 45.24,40.42 45.1,40.28 44.89,40.28 44.74,40.42 44.74,41.87 44.41,42.21 43.71,42.21 43.38,41.89 43.38,38.41 43.11,38.13 41.09,38.13 v1(40.79,38.42)
MIPI_CSI_RX_D1P: length 177.9
  TOP w0.124: v1(52.76,55.53) 52.46,55.83 51.21,55.83 49.87,57.16 49.87,58.16 49.78,58.25 J3.72
  ART03 w0.113: v1(154.54,53.48) 154.26,53.77 153.85,53.77 153.64,53.57 153.64,50.22 153.27,49.85 135.32,49.85 135.13,49.65 135.13,43.36 134.65,42.89 123.92,42.89 123.67,42.64 123.67,38.28 123.26,37.87 85.66,37.87 85.33,38.2 42.88,38.2 42.49,37.81 41.09,37.81 v1(40.79,37.51)
  BOTTOM w0.124: v1(40.79,37.51) 41.09,37.8 43.24,37.8 43.71,38.27 43.71,41.75 43.84,41.88 44.27,41.88 44.42,41.74 44.42,40.29 44.75,39.95 45.23,39.95 45.57,40.29 45.57,41.74 45.71,41.88 45.92,41.88 46.06,41.74 46.06,40.29 46.4,39.95 46.88,39.95 47.21,40.29 47.21,41.74 47.36,41.88 47.56,41.88 47.71,41.74 47.71,40.29 48.05,39.95 48.52,39.95 48.86,40.29 48.86,41.74 49,41.88 51.31,41.88 51.69,42.26 51.69,55.67 51.84,55.83 52.46,55.83 v1(52.76,55.53) ; v1(154.54,53.48) 154.25,53.77 153.92,53.77 153.32,54.37 152.36,54.37 152.27,54.28 J22.7
MIPI_CSI_RX_D2N: length 171.2
  TOP w0.124: v1(146.05,75.68) 145.77,75.39 144.95,75.39 144.24,76.11 144.24,76.37 v1(144.52,76.65) ; J3.69 49.28,64.63 49.2,64.72 49.2,67.1 49.48,67.38 55.65,67.38 55.91,67.13 55.91,65.24 v1(55.61,64.94)
  ART03 w0.113: v1(55.61,64.94) 55.91,64.64 55.91,63.98 56.28,63.61 59.66,63.61 60.14,63.13 60.14,54.54 60.01,54.41 59.05,54.41 58.73,54.1 58.73,53.65 59.05,53.33 60.01,53.33 60.14,53.2 60.14,53.01 60.01,52.88 59.05,52.88 58.73,52.56 58.73,52.11 59.05,51.8 60.01,51.8 60.14,51.66 60.14,51.48 60.01,51.34 59.05,51.34 58.73,51.03 58.73,50.49 59.05,50.16 94.08,50.16 94.8,50.88 94.8,54.7 95.21,55.11 97.92,55.11 98.39,55.58 98.39,61.71 98.95,62.28 110.76,62.28 111.26,62.78 111.26,69.11 111.61,69.45 116.27,69.45 117.34,70.52 126.65,70.52 127.01,70.88 127.01,74.53 127.24,74.76 143.6,74.76 144.23,75.4 144.23,76.37 v1(144.52,76.65)
  BOTTOM w0.124: R227.1 147.09,59.19 145.42,59.19 145.21,59.41 145.21,70.61 143.89,71.93 143.89,75.38 144.22,75.71 144.22,76.35 v1(144.52,76.65) ; v1(146.05,75.68) 146.34,75.39 147.11,75.39 R233.1
MIPI_CSI_RX_D2P: length 172.3
  TOP w0.124: v1(56.53,64.94) 56.23,65.24 56.23,67.26 55.79,67.71 49.34,67.71 48.87,67.24 48.87,64.72 48.78,64.63 J3.67 ; v1(143.63,76.65) 143.91,76.37 143.91,75.97 144.82,75.07 145.77,75.07 v1(146.05,74.79)
  ART03 w0.113: v1(143.63,76.65) 143.92,76.37 143.92,75.53 143.47,75.08 127.11,75.08 126.7,74.66 126.7,71.01 126.52,70.84 117.21,70.84 116.14,69.77 111.48,69.77 110.95,69.24 110.95,62.91 110.63,62.6 98.82,62.6 98.07,61.85 98.07,55.71 97.79,55.43 95.08,55.43 94.49,54.83 94.49,51.01 93.95,50.48 59.19,50.48 59.04,50.62 59.04,50.9 59.18,51.03 60.14,51.03 60.46,51.35 60.46,51.79 60.14,52.11 59.18,52.11 59.04,52.24 59.04,52.43 59.18,52.56 60.14,52.56 60.46,52.88 60.46,53.33 60.14,53.65 59.18,53.65 59.04,53.78 59.04,53.96 59.18,54.1 60.14,54.1 60.46,54.41 60.46,63.26 59.79,63.93 56.41,63.93 56.23,64.11 56.23,64.64 v1(56.53,64.94)
  BOTTOM w0.124: v1(146.05,74.79) 146.34,75.07 147.11,75.07 R232.1 ; v1(143.63,76.65) 143.89,76.39 143.89,75.85 143.56,75.52 143.56,71.8 144.88,70.47 144.88,59.27 145.29,58.87 147.09,58.87 R226.1
MIPI_CSI_RX_D3N: length 162.9
  TOP w0.124: J3.73 50.28,64.63 50.2,64.72 50.2,66.27 50.48,66.54 54.62,66.54 54.74,66.42 54.74,62.88 v1(54.44,62.58)
  ART03 w0.113: v1(146.05,73.18) 145.77,72.89 145.22,72.89 144.87,72.54 144.87,70.95 144.68,70.76 144.44,70.76 arc(144.36,70.79) 144.32,70.87 arc(144.29,70.96) 144.21,70.99 143.99,70.99 arc(143.91,70.96) 143.87,70.87 arc(143.84,70.79) 143.76,70.76 143.54,70.76 arc(143.46,70.79) 143.42,70.87 arc(143.39,70.96) 143.31,70.99 143.09,70.99 arc(143,70.96) 142.97,70.87 arc(142.94,70.79) 142.86,70.76 142.58,70.76 arc(142.52,70.78) 142.5,70.84 arc(142.48,70.89) 142.42,70.91 142.12,70.91 arc(142.07,70.89) 142.05,70.84 arc(142.03,70.78) 141.97,70.76 141.73,70.76 arc(141.65,70.79) 141.62,70.87 arc(141.58,70.96) 141.5,70.99 141.28,70.99 arc(141.2,70.96) 141.17,70.87 arc(141.13,70.79) 141.05,70.76 140.83,70.76 arc(140.75,70.79) 140.72,70.87 arc(140.68,70.96) 140.6,70.99 140.38,70.99 arc(140.3,70.96) 140.26,70.87 arc(140.23,70.79) 140.15,70.76 139.93,70.76 arc(139.85,70.79) 139.81,70.87 arc(139.78,70.96) 139.7,70.99 139.48,70.99 arc(139.4,70.96) 139.36,70.87 arc(139.33,70.79) 139.25,70.76 139.03,70.76 arc(138.94,70.79) 138.91,70.87 arc(138.88,70.96) 138.8,70.99 138.57,70.99 arc(138.49,70.96) 138.46,70.87 arc(138.43,70.79) 138.35,70.76 138.12,70.76 arc(138.04,70.79) 138.01,70.87 arc(137.98,70.96) 137.89,70.99 137.67,70.99 arc(137.59,70.96) 137.56,70.87 arc(137.52,70.79) 137.44,70.76 137.22,70.76 arc(137.14,70.79) 137.11,70.87 arc(137.07,70.96) 136.99,70.99 136.77,70.99 arc(136.69,70.96) 136.66,70.87 arc(136.62,70.79) 136.54,70.76 136.32,70.76 arc(136.24,70.79) 136.2,70.87 arc(136.17,70.96) 136.09,70.99 135.87,70.99 arc(135.79,70.96) 135.75,70.87 arc(135.72,70.79) 135.64,70.76 135.4,70.76 arc(135.33,70.79) 135.3,70.86 arc(135.27,70.93) 135.2,70.96 134.95,70.96 arc(134.88,70.93) 134.85,70.86 arc(134.82,70.79) 134.74,70.76 133.38,70.76 132.86,70.24 132.86,68.15 132.51,67.8 114.97,67.8 114.05,66.87 114.05,60.73 113.49,60.18 101.66,60.18 101.04,59.56 101.04,53.45 100.46,52.86 96.96,52.86 96.58,52.48 96.58,48.76 96.03,48.22 51.77,48.22 51.24,48.74 51.24,62.98 51.74,63.49 54.49,63.49 54.75,63.23 54.75,62.89 v1(54.44,62.58)
  BOTTOM w0.124: R229.1 147.08,64.49 146.15,64.49 145.77,64.86 145.77,71.08 145.04,71.82 145.04,72.58 145.35,72.89 145.77,72.89 v1(146.05,73.18) 146.34,72.89 147.11,72.89 R231.1
MIPI_CSI_RX_D3P: length 161.7
  TOP w0.124: v1(55.37,62.58) 55.07,62.88 55.07,66.56 54.75,66.87 50.34,66.87 49.87,66.4 49.87,64.72 49.78,64.63 J3.71
  ART03 w0.113: v1(55.37,62.58) 55.06,62.89 55.06,63.36 54.63,63.8 51.61,63.8 50.93,63.12 50.93,48.61 51.64,47.9 96.16,47.9 96.89,48.63 96.89,52.35 97.09,52.55 100.59,52.55 101.36,53.32 101.36,59.43 101.79,59.86 113.62,59.86 114.36,60.6 114.36,66.74 115.1,67.48 132.64,67.48 133.17,68.02 133.17,70.11 133.51,70.44 144.81,70.44 145.19,70.82 145.19,72.41 145.35,72.57 145.77,72.57 v1(146.05,72.29)
  BOTTOM w0.124: R228.1 147.09,64.81 146.28,64.81 146.1,64.99 146.1,71.22 145.36,71.95 145.36,72.44 145.49,72.57 145.77,72.57 v1(146.05,72.29) 146.34,72.57 147.11,72.57 R230.1
MIPI_DSI_TX0_CLKN: length 148.4
  TOP w0.124: v1(44.63,69.03) 44.37,68.78 44.37,67.75 45.23,66.89 45.23,65.01 45.21,64.71 45.28,64.63 J3.53 ; v1(155.73,76.12) 155.45,75.84 152.41,75.84 152.32,75.93 J23.24
  ART03 w0.113: v1(44.63,69.03) 44.32,68.73 44.32,68.16 44.48,68 45.79,68 45.99,68.2 45.99,68.83 46.3,69.15 53.43,69.15 53.62,69.34 53.62,70.28 54.16,70.82 61.52,70.82 62.22,70.13 80.46,70.13 82.39,68.2 93.19,68.2 94.28,69.29 100.36,69.29 100.67,69.61 100.67,76.41 101.61,77.35 120.95,77.35 121.57,77.97 136.27,77.97 136.87,78.57 138.31,78.57 138.55,78.8 138.55,81.38 139.02,81.86 146.48,81.86 146.8,82.18 146.8,83.22 147.11,83.54 147.56,83.54 147.88,83.22 147.88,82.18 148.01,82.05 148.2,82.05 148.33,82.18 148.33,83.22 148.65,83.54 149.1,83.54 149.41,83.22 149.41,82.18 149.55,82.05 150.96,82.05 151.32,81.69 151.32,75.91 151.43,75.8 155.41,75.8 v1(155.73,76.12)
MIPI_DSI_TX0_CLKP: length 149.8
  TOP w0.124: v1(155.73,75.23) 155.45,75.51 152.41,75.51 152.32,75.43 J23.23 ; v1(43.73,69.05) 44.04,68.74 44.04,67.61 44.9,66.75 44.9,65.03 44.88,64.73 44.78,64.63 J3.51
  ART03 w0.113: v1(43.73,69.05) 43.73,69 44.01,68.73 44.01,68.03 44.35,67.69 45.92,67.69 46.3,68.07 46.3,68.7 46.43,68.83 53.56,68.83 53.94,69.21 53.94,70.15 54.29,70.51 61.39,70.51 62.09,69.81 80.33,69.81 82.26,67.88 93.32,67.88 94.42,68.97 100.49,68.97 100.99,69.48 100.99,76.28 101.74,77.03 121.08,77.03 121.71,77.66 136.4,77.66 137,78.25 138.45,78.25 138.86,78.67 138.86,81.25 139.16,81.54 146.61,81.54 147.11,82.05 147.11,83.09 147.25,83.22 147.43,83.22 147.56,83.09 147.56,82.05 147.88,81.73 148.33,81.73 148.65,82.05 148.65,83.09 148.78,83.22 148.97,83.22 149.1,83.09 149.1,82.05 149.42,81.73 150.83,81.73 151,81.56 151,80.33 arc(150.97,80.24) 150.88,80.2 arc(150.79,80.16) 150.75,80.07 150.75,79.87 arc(150.79,79.78) 150.88,79.75 arc(150.97,79.71) 151,79.62 151,79.42 arc(150.97,79.33) 150.88,79.3 arc(150.79,79.26) 150.75,79.17 150.75,78.97 arc(150.79,78.88) 150.88,78.84 arc(150.97,78.81) 151,78.72 151,78.52 arc(150.97,78.43) 150.88,78.39 arc(150.79,78.36) 150.75,78.27 150.75,78.07 arc(150.79,77.98) 150.88,77.94 arc(150.97,77.91) 151,77.82 151,75.78 151.3,75.48 155.47,75.48 v1(155.73,75.23)
MIPI_DSI_TX0_D0N: length 149.2
  TOP w0.124: J3.43 42.78,64.63 42.7,64.72 42.7,69.95 42.95,70.2 44.33,70.2 44.78,70.65 44.78,72.3 v1(45.08,72.6) ; v1(153.57,77.62) 153.29,77.34 152.41,77.34 152.32,77.43 J23.27
  ART03 w0.113: v1(45.08,72.6) 44.78,72.3 44.78,70.38 45.1,70.06 46.66,70.06 46.93,70.33 46.93,72.3 47.38,72.75 50.14,72.75 50.57,72.32 50.57,70.83 50.71,70.7 50.89,70.7 51.02,70.83 51.02,71.76 51.34,72.08 63.06,72.08 64.12,71.01 82.16,71.01 83.05,70.13 99.06,70.13 99.43,70.5 99.43,77.8 100.19,78.56 119.86,78.56 120.89,79.59 136.28,79.59 136.55,79.85 136.55,82.38 136.85,82.67 141.01,82.67 142.64,84.31 151.69,84.31 152.2,83.81 152.2,82.66 arc(152.23,82.58) 152.3,82.55 arc(152.37,82.52) 152.4,82.45 152.4,82.2 arc(152.37,82.13) 152.3,82.1 arc(152.23,82.07) 152.2,82 152.2,81.75 arc(152.23,81.68) 152.3,81.65 arc(152.37,81.62) 152.4,81.55 152.4,81.3 arc(152.37,81.23) 152.3,81.2 arc(152.23,81.17) 152.2,81.1 152.2,77.45 152.31,77.34 153.29,77.34 v1(153.57,77.62)
MIPI_DSI_TX0_D0P: length 149.6
  TOP w0.124: J23.26 152.32,76.93 152.41,77.01 153.29,77.01 v1(153.57,76.73) ; J3.41 42.28,64.63 42.37,64.72 42.37,70.08 42.82,70.53 44.19,70.53 44.45,70.79 44.45,72.3 v1(44.15,72.6)
  ART03 w0.113: v1(44.15,72.6) 44.46,72.28 44.46,71.36 arc(44.43,71.28) 44.36,71.25 arc(44.28,71.22) 44.25,71.14 44.25,70.91 arc(44.28,70.83) 44.36,70.8 arc(44.43,70.77) 44.46,70.69 44.46,70.25 44.97,69.74 46.79,69.74 47.24,70.2 47.24,72.17 47.51,72.44 50.01,72.44 50.26,72.19 50.26,70.7 50.57,70.38 51.02,70.38 51.34,70.7 51.34,71.63 51.47,71.77 62.93,71.77 63.99,70.7 82.03,70.7 82.92,69.81 99.19,69.81 99.75,70.36 99.75,77.67 100.32,78.24 119.99,78.24 121.02,79.27 136.41,79.27 136.87,79.72 136.87,82.24 136.98,82.36 141.14,82.36 142.77,83.99 151.56,83.99 151.88,83.67 151.88,77.32 152.18,77.02 153.27,77.02 v1(153.57,76.73)
MIPI_DSI_TX0_D1N: length 150.2
  TOP w0.124: v1(43.78,64.95) 43.78,64.94 J3.47 ; v1(153.57,74.62) 153.29,74.34 152.41,74.34 152.32,74.43 J23.21
  ART03 w0.113: v1(43.78,64.95) 43.47,65.25 43.02,65.25 42.72,65.55 42.72,66.44 43.31,67.03 46.87,67.03 47.01,67.16 47.01,67.85 47.32,68.17 47.77,68.17 48.09,67.85 48.09,67.16 48.22,67.03 48.41,67.03 48.54,67.16 48.54,67.85 48.86,68.17 49.31,68.17 49.62,67.85 49.62,67.16 49.76,67.03 49.94,67.03 50.07,67.16 50.07,67.85 50.39,68.17 50.84,68.17 51.16,67.85 51.16,67.16 51.29,67.03 53.83,67.03 55.34,68.54 79.21,68.54 80.47,67.28 101.32,67.28 101.97,67.93 101.97,75.3 102.79,76.12 122.03,76.12 122.7,76.79 139.61,76.79 140.18,77.36 140.18,80.64 140.51,80.97 148.13,80.97 148.57,80.53 148.57,79.34 148.7,79.21 149.44,79.21 149.76,78.89 149.76,78.44 149.44,78.13 148.27,78.13 148.11,77.97 148.11,77.79 148.23,77.67 149.44,77.67 149.76,77.36 149.76,76.91 149.44,76.59 148.27,76.59 148.11,76.43 148.11,76.25 148.23,76.14 149.44,76.14 149.76,75.82 149.76,75.37 149.44,75.06 148.27,75.06 148.11,74.9 148.11,74.45 148.23,74.33 153.46,74.33 153.57,74.45 v1(153.57,74.62)
MIPI_DSI_TX0_D1P: length 150.7
  TOP w0.124: v1(153.57,73.73) 153.29,74.01 152.41,74.01 152.32,73.93 J23.20 ; v1(43.78,65.88) 43.28,65.38 J3.45
  ART03 w0.113: v1(43.78,65.88) 43.47,65.57 43.15,65.57 43.04,65.68 43.04,66.31 43.44,66.71 44.12,66.71 arc(44.19,66.68) 44.23,66.6 arc(44.26,66.53) 44.33,66.49 44.57,66.49 arc(44.64,66.53) 44.68,66.6 arc(44.71,66.68) 44.79,66.71 45.02,66.71 arc(45.1,66.68) 45.13,66.6 arc(45.16,66.53) 45.24,66.49 45.47,66.49 arc(45.55,66.53) 45.58,66.6 arc(45.61,66.68) 45.69,66.71 47.01,66.71 47.32,67.03 47.32,67.72 47.45,67.85 47.64,67.85 47.77,67.72 47.77,67.03 48.09,66.71 48.54,66.71 48.86,67.03 48.86,67.72 48.99,67.85 49.18,67.85 49.31,67.72 49.31,67.03 49.62,66.71 50.07,66.71 50.39,67.03 50.39,67.72 50.52,67.85 50.71,67.85 50.84,67.72 50.84,67.03 51.16,66.71 53.96,66.71 55.47,68.22 79.08,68.22 80.34,66.96 101.45,66.96 102.29,67.8 102.29,75.17 102.92,75.8 122.16,75.8 122.83,76.48 139.74,76.48 140.5,77.23 140.5,80.51 140.64,80.66 148,80.66 148.25,80.4 148.25,79.21 148.57,78.89 149.31,78.89 149.44,78.76 149.44,78.57 149.31,78.44 148.14,78.44 147.8,78.1 147.8,77.65 148.09,77.36 149.31,77.36 149.44,77.23 149.44,77.04 149.31,76.91 148.14,76.91 147.8,76.56 147.8,76.12 148.09,75.82 149.31,75.82 149.44,75.69 149.44,75.5 149.31,75.37 148.14,75.37 147.8,75.03 147.8,74.32 148.09,74.02 153.28,74.02 v1(153.57,73.73)
MIPI_DSI_TX0_D2N: length 149.3
  TOP w0.124: v1(46.28,65.95) 46.78,65.44 J3.59 ; J23.18 152.32,72.93 152.41,72.84 155.45,72.84 v1(155.73,73.12)
  ART03 w0.113: v1(46.28,65.95) 46.62,65.61 54.06,65.61 55.47,67.01 62.76,67.01 63.28,67.53 78.41,67.53 80.14,65.81 101.46,65.81 102.81,67.16 102.81,74.28 103.28,74.75 118.47,74.75 118.78,74.43 118.78,73.7 118.92,73.57 119.1,73.57 119.23,73.7 119.23,74.43 119.55,74.75 120,74.75 120.32,74.43 120.32,73.7 120.45,73.57 120.64,73.57 120.77,73.7 120.77,74.43 121.09,74.75 121.53,74.75 121.85,74.43 121.85,73.7 121.98,73.57 122.17,73.57 122.3,73.7 122.3,74.43 122.62,74.75 124.03,74.75 125.33,76.05 141.08,76.05 141.26,76.24 141.26,77.39 141.59,77.72 143.45,77.72 143.59,77.85 143.59,79.08 143.9,79.4 144.35,79.4 144.67,79.08 144.67,77.85 144.8,77.72 144.99,77.72 145.12,77.85 145.12,79.08 145.44,79.4 145.89,79.4 146.2,79.08 146.2,77.85 146.34,77.72 146.8,77.72 147.15,77.37 147.15,73.06 147.38,72.83 152.31,72.83 152.62,72.52 152.62,71.34 152.76,71.2 152.94,71.2 153.07,71.34 153.07,72.52 153.39,72.83 153.84,72.83 154.16,72.52 154.16,71.34 154.29,71.2 154.48,71.2 154.61,71.34 154.61,72.52 154.93,72.83 155.44,72.83 v1(155.73,73.12)
MIPI_DSI_TX0_D2P: length 149.7
  TOP w0.124: J23.17 152.32,72.43 152.41,72.51 155.45,72.51 v1(155.73,72.23) ; v1(46.28,64.95) 46.28,64.94 J3.57
  ART03 w0.113: v1(155.73,72.23) 155.44,72.52 155.06,72.52 154.92,72.38 154.92,71.21 154.61,70.89 154.16,70.89 153.84,71.21 153.84,72.38 153.71,72.52 153.52,72.52 153.39,72.38 153.39,71.21 153.07,70.89 152.62,70.89 152.31,71.21 152.31,72.38 152.18,72.52 151.85,72.52 arc(151.77,72.48) 151.74,72.4 arc(151.7,72.32) 151.62,72.28 151.4,72.28 arc(151.32,72.32) 151.28,72.4 arc(151.25,72.48) 151.17,72.52 150.95,72.52 arc(150.87,72.48) 150.83,72.4 arc(150.8,72.32) 150.72,72.28 150.5,72.28 arc(150.42,72.32) 150.38,72.4 arc(150.35,72.48) 150.27,72.52 150.05,72.52 arc(149.96,72.48) 149.93,72.4 arc(149.9,72.32) 149.81,72.28 149.6,72.28 arc(149.51,72.32) 149.48,72.4 arc(149.45,72.48) 149.36,72.52 149.14,72.52 arc(149.06,72.48) 149.03,72.4 arc(148.99,72.32) 148.91,72.28 148.69,72.28 arc(148.61,72.32) 148.58,72.4 arc(148.54,72.48) 148.46,72.52 147.25,72.52 146.84,72.93 146.84,77.24 146.67,77.4 146.21,77.4 145.89,77.72 145.89,78.95 145.76,79.08 145.57,79.08 145.44,78.95 145.44,77.72 145.12,77.4 144.67,77.4 144.35,77.72 144.35,78.95 144.22,79.08 144.04,79.08 143.9,78.95 143.9,77.72 143.59,77.4 141.72,77.4 141.58,77.26 141.58,76.1 141.21,75.74 125.47,75.74 124.16,74.43 122.75,74.43 122.62,74.3 122.62,73.57 122.3,73.25 121.85,73.25 121.54,73.57 121.54,74.3 121.4,74.43 121.22,74.43 121.08,74.3 121.08,73.57 120.77,73.25 120.32,73.25 120,73.57 120,74.3 119.87,74.43 119.68,74.43 119.55,74.3 119.55,73.57 119.23,73.25 118.78,73.25 118.47,73.57 118.47,74.3 118.34,74.43 103.41,74.43 103.12,74.15 103.12,67.03 101.59,65.49 80.01,65.49 78.28,67.22 63.41,67.22 62.89,66.7 55.6,66.7 54.19,65.29 49.72,65.29 arc(49.66,65.27) 49.63,65.21 arc(49.61,65.15) 49.55,65.12 49.27,65.12 arc(49.21,65.15) 49.18,65.21 arc(49.16,65.27) 49.1,65.29 48.81,65.29 arc(48.76,65.27) 48.73,65.21 arc(48.71,65.15) 48.65,65.12 48.36,65.12 arc(48.3,65.15) 48.28,65.21 arc(48.25,65.27) 48.19,65.29 47.91,65.29 arc(47.85,65.27) 47.83,65.21 arc(47.8,65.15) 47.74,65.12 47.46,65.12 arc(47.4,65.15) 47.38,65.21 arc(47.35,65.27) 47.29,65.29 46.62,65.29 v1(46.28,64.95)
MIPI_DSI_TX0_D3N: length 149.6
  TOP w0.124: v1(155.73,79.12) 155.45,78.84 152.41,78.84 152.32,78.93 J23.30 ; v1(47.97,73.96) 47.7,73.69 47.7,72.99 arc(47.72,72.93) 47.79,72.9 arc(47.85,72.88) 47.88,72.81 47.88,72.5 arc(47.85,72.43) 47.79,72.41 arc(47.72,72.38) 47.7,72.32 47.7,72 arc(47.72,71.94) 47.79,71.91 arc(47.85,71.88) 47.88,71.82 47.88,71.51 arc(47.85,71.44) 47.79,71.42 arc(47.72,71.39) 47.7,71.33 47.7,71.01 arc(47.72,70.95) 47.79,70.92 arc(47.85,70.89) 47.88,70.83 47.88,70.51 arc(47.85,70.45) 47.79,70.42 arc(47.72,70.4) 47.7,70.33 47.7,70.02 arc(47.72,69.95) 47.79,69.93 arc(47.85,69.9) 47.88,69.84 47.88,69.52 arc(47.85,69.46) 47.79,69.43 arc(47.72,69.41) 47.7,69.34 47.7,69.03 arc(47.72,68.96) 47.79,68.94 arc(47.85,68.91) 47.88,68.85 47.88,68.53 arc(47.85,68.47) 47.79,68.44 arc(47.72,68.41) 47.7,68.35 47.7,68.04 arc(47.72,67.97) 47.79,67.95 arc(47.85,67.92) 47.88,67.85 47.88,67.54 arc(47.85,67.48) 47.79,67.45 arc(47.72,67.42) 47.7,67.36 47.7,67.04 arc(47.72,66.98) 47.79,66.95 arc(47.85,66.93) 47.88,66.86 47.88,66.55 arc(47.85,66.48) 47.79,66.46 arc(47.72,66.43) 47.7,66.37 47.7,64.72 47.78,64.63 J3.63
  ART03 w0.113: v1(47.97,73.96) 47.67,74.27 47.67,74.6 47.78,74.71 57.26,74.71 57.39,74.59 57.39,73.09 57.8,72.68 63.84,72.68 64.93,71.59 69.92,71.59 72.06,73.73 74.66,73.73 76.48,71.92 82.5,71.92 83.44,70.98 98.12,70.98 98.46,71.32 98.46,79.15 98.85,79.54 120.22,79.54 120.79,80.11 135.52,80.11 135.97,80.55 135.97,83.33 137.56,84.92 152.72,84.92 153.57,84.07 153.57,83.6 arc(153.54,83.54) 153.48,83.51 arc(153.42,83.49) 153.39,83.42 153.39,83.15 arc(153.42,83.09) 153.48,83.06 arc(153.54,83.04) 153.57,82.97 153.57,82.7 arc(153.54,82.64) 153.48,82.61 arc(153.42,82.58) 153.39,82.52 153.39,82.25 arc(153.42,82.19) 153.48,82.16 arc(153.54,82.13) 153.57,82.07 153.57,81.8 arc(153.54,81.73) 153.48,81.71 arc(153.42,81.68) 153.39,81.62 153.39,81.35 arc(153.42,81.28) 153.48,81.26 arc(153.54,81.23) 153.57,81.17 153.57,80.73 153.96,80.34 154.39,80.34 arc(154.47,80.3) 154.5,80.22 arc(154.54,80.14) 154.62,80.11 154.84,80.11 arc(154.92,80.14) 154.95,80.22 arc(154.99,80.3) 155.07,80.34 155.29,80.34 arc(155.37,80.3) 155.41,80.22 arc(155.44,80.14) 155.52,80.11 155.74,80.11 arc(155.82,80.14) 155.86,80.22 arc(155.89,80.3) 155.97,80.34 156.31,80.34 156.51,80.13 156.51,78.99 156.36,78.83 156.01,78.83 v1(155.73,79.12)
MIPI_DSI_TX0_D3P: length 148.6
  TOP w0.124: v1(47.04,73.96) 47.37,73.64 47.37,64.72 47.28,64.63 J3.61 ; J23.29 152.32,78.42 152.41,78.51 155.45,78.51 v1(155.73,78.23)
  ART03 w0.113: v1(47.04,73.96) 47.35,74.27 47.35,74.73 47.65,75.03 57.39,75.03 57.7,74.72 57.7,73.22 57.93,73 63.97,73 65.06,71.9 69.78,71.9 71.93,74.05 74.79,74.05 76.61,72.23 82.63,72.23 83.57,71.29 97.99,71.29 98.15,71.45 98.15,79.28 98.71,79.85 120.09,79.85 120.66,80.42 135.39,80.42 135.65,80.68 135.65,83.46 137.42,85.24 152.85,85.24 153.88,84.2 153.88,80.86 154.09,80.65 156.44,80.65 156.83,80.26 156.83,78.86 156.49,78.52 156.01,78.52 v1(155.73,78.23)
MIPI_DSI_TX1_CLKN: length 208
  TOP w0.124: J3.27 38.78,64.63 38.7,64.72 38.7,68.31 36.89,70.12 18.38,70.12 v1(18.06,70.45) ; J26.24 150.64,53.19 150.55,53.11 133.61,53.11 130.46,56.25 118.84,56.25 v1(118.57,56.53)
  ART03 w0.113: v1(118.57,56.53) 118.27,56.23 114,56.23 113.55,55.79 113.55,55.23 113.42,55.1 112.28,55.1 111.96,54.78 111.96,54.33 112.28,54.02 113.42,54.02 113.55,53.88 113.55,53.7 113.42,53.56 112.28,53.56 111.96,53.25 111.96,52.8 112.28,52.48 113.42,52.48 113.55,52.35 113.55,52.16 113.42,52.03 112.28,52.03 111.96,51.71 111.96,51.26 112.28,50.95 113.42,50.95 113.55,50.82 113.55,50.63 113.42,50.5 112.28,50.5 111.96,50.18 111.96,49.73 112.28,49.41 113.42,49.41 113.55,49.28 113.55,48.79 113.38,48.62 110.49,48.62 110.06,48.2 110.06,44.11 109.82,43.86 92.14,43.86 91.46,44.54 45.31,44.54 42.93,46.92 19.34,46.92 19.15,47.11 19.15,69.81 18.83,70.14 18.37,70.14 v1(18.06,70.45)
MIPI_DSI_TX1_CLKP: length 207.9
  TOP w0.124: J26.23 150.64,52.69 150.55,52.78 133.48,52.78 130.33,55.93 118.85,55.93 v1(118.57,55.64) ; J3.25 38.28,64.63 38.37,64.72 38.37,68.18 36.75,69.8 18.33,69.8 v1(18.06,69.52)
  ART03 w0.113: v1(118.57,55.64) 118.29,55.92 114.13,55.92 113.87,55.66 113.87,55.1 113.55,54.78 112.41,54.78 112.28,54.65 112.28,54.46 112.41,54.33 113.55,54.33 113.87,54.01 113.87,53.57 113.55,53.25 112.41,53.25 112.28,53.12 112.28,52.93 112.41,52.8 113.55,52.8 113.87,52.48 113.87,52.03 113.55,51.71 112.41,51.71 112.28,51.58 112.28,51.4 112.41,51.26 113.55,51.26 113.87,50.95 113.87,50.5 113.55,50.18 112.41,50.18 112.28,50.05 112.28,49.86 112.41,49.73 113.55,49.73 113.87,49.41 113.87,48.66 113.51,48.31 112.8,48.31 arc(112.72,48.27) 112.68,48.19 arc(112.65,48.11) 112.57,48.08 112.35,48.08 arc(112.27,48.11) 112.23,48.19 arc(112.2,48.27) 112.12,48.31 111.9,48.31 arc(111.82,48.27) 111.78,48.19 arc(111.75,48.11) 111.67,48.08 111.45,48.08 arc(111.36,48.11) 111.33,48.19 arc(111.3,48.27) 111.22,48.31 110.62,48.31 110.37,48.06 110.37,43.97 109.95,43.55 92.01,43.55 91.33,44.23 45.18,44.23 42.8,46.61 19.21,46.61 18.84,46.98 18.84,69.68 18.7,69.82 18.36,69.82 v1(18.06,69.52)
MIPI_DSI_TX1_D0N: length 207.4
  TOP w0.124: J26.27 150.64,54.69 150.55,54.61 133.91,54.61 130.92,57.6 117.27,57.6 v1(116.97,57.9) ; v1(19.89,67.66) 20.19,67.36 35.84,67.36 36.2,67 36.2,64.72 36.28,64.63 J3.17
  ART03 w0.113: v1(19.89,67.66) 20.18,67.37 20.56,67.37 20.94,66.99 20.94,48.47 21.16,48.25 32.54,48.25 32.66,48.37 32.66,49.77 32.97,50.08 33.42,50.08 33.74,49.77 33.74,48.41 33.9,48.25 34.08,48.25 34.19,48.37 34.19,49.77 34.51,50.08 34.96,50.08 35.27,49.77 35.27,48.41 35.43,48.25 35.61,48.25 35.73,48.37 35.73,49.77 36.04,50.08 36.49,50.08 36.81,49.77 36.81,48.41 36.97,48.25 37.15,48.25 37.26,48.37 37.26,49.77 37.58,50.08 38.03,50.08 38.34,49.77 38.34,48.41 38.5,48.25 38.68,48.25 38.79,48.37 38.79,49.77 39.11,50.08 39.56,50.08 39.88,49.77 39.88,48.41 40.03,48.25 40.22,48.25 40.33,48.37 40.33,49.77 40.65,50.08 41.09,50.08 41.41,49.77 41.41,48.41 41.57,48.25 41.75,48.25 41.86,48.37 41.86,49.77 42.18,50.08 42.63,50.08 42.95,49.77 42.95,48.41 43.1,48.25 43.55,48.25 46.12,45.69 92.56,45.69 93.23,45.02 108.28,45.02 108.4,45.13 108.4,50.42 108.86,50.88 110.37,50.88 110.48,51 110.48,57.15 110.92,57.59 116.66,57.59 v1(116.97,57.9)
